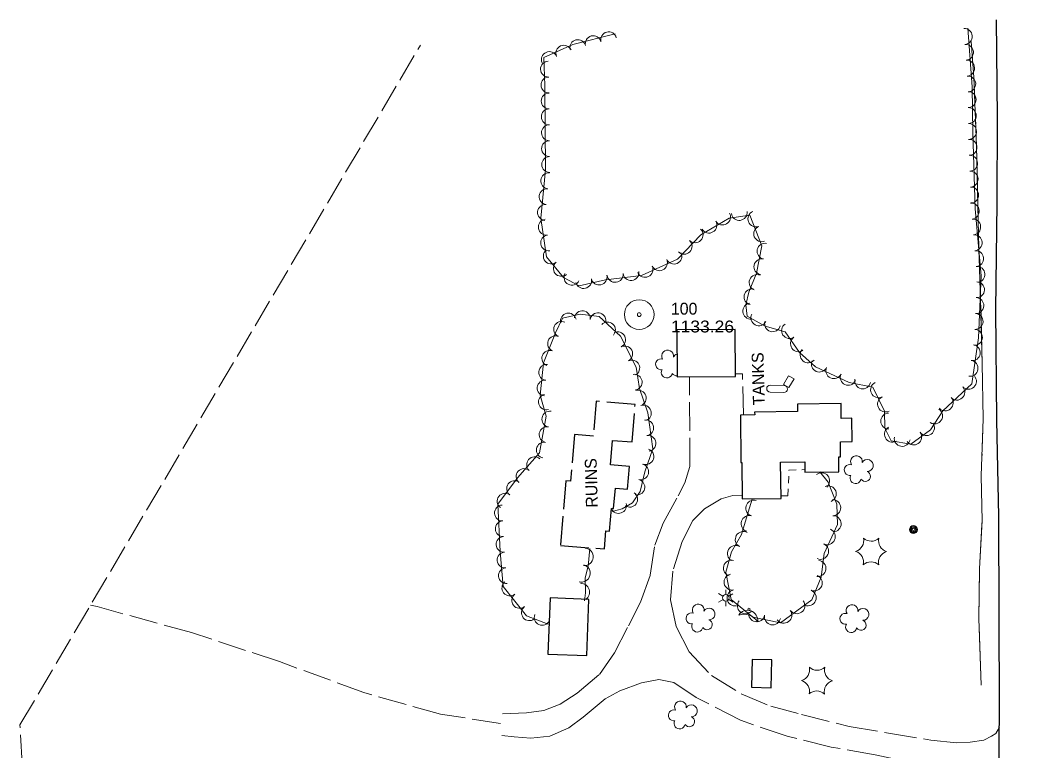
# Model space of a CAD drawing. Extents: x 296527 to 298902, y 45711 to 46924.
# Drawn here: x 297194 to 297699, y 46546 to 46914 of the extents above; entities that cross this region are included whole.
import ezdxf

# ---------------------------------------------------------------- set-up
doc = ezdxf.new("R2010")
doc.units = 0
doc.header["$LTSCALE"] = 2.4
doc.linetypes.add('LONG_DASHED', pattern=[7.5, 6, -1.5])
doc.linetypes.add('SHORT_DASHED', pattern=[2.7, 1.5, -1.2])
for name, color, linetype, lineweight in [('11', 7, 'Continuous', 25), ('12', 7, 'Continuous', 13), ('14', 7, 'Continuous', 13), ('17', 7, 'LONG_DASHED', 13), ('18', 7, 'Continuous', 13), ('19', 7, 'Continuous', 13), ('4', 7, 'Continuous', 13), ('6', 7, 'Continuous', 13)]:
    doc.layers.add(name, color=color, linetype=linetype, lineweight=lineweight)

msp = doc.modelspace()

# ---------------------------------------------------------------- linework, layer by layer
at = {"layer": '11'}
msp.add_lwpolyline([(297692.464, 45930.163), (297697.156, 45968.357), (297698.514, 45980.054), (297696.031, 46018.05), (297694.427, 46060.322), (297693.685, 46107.184), (297690.534, 46150.067), (297687.278, 46195.408), (297686.38, 46235.432), (297685.597, 46280.048), (297686.183, 46328.589), (297686.8, 46372.646), (297687.26, 46409.842), (297687.847, 46444.997), (297688.271, 46486.097), (297688.584, 46512.367), (297689.185, 46567.008), (297689.042, 46613.28), (297688.816, 46663.597), (297687.713, 46712.034), (297687.351, 46767.843), (297688.042, 46821.878), (297688.175, 46864.957), (297687.551, 46914.245)], dxfattribs=at)
at = {"layer": '12'}
for p, q in [((297573.172, 46726.37), (297580.192, 46726.161)), ((297580.272, 46729.661), (297573.178, 46729.867))]:
    msp.add_line(p, q, dxfattribs=at)
at = {"layer": '12', "lineweight": 25}
for points in [[(297526.256, 46734.025), (297555.648, 46734.199), (297555.507, 46757.95), (297526.115, 46757.776)], [(297590.797, 46685.955), (297607.985, 46686.138), (297607.905, 46693.67), (297608.8, 46693.679), (297608.719, 46701.263), (297614.672, 46701.326), (297614.547, 46713.1), (297609.168, 46713.043), (297609.088, 46720.521), (297587.031, 46720.286), (297587.072, 46716.494), (297565.396, 46716.264), (297565.411, 46714.818), (297558.239, 46714.742), (297558.493, 46690.847), (297558.925, 46690.852), (297559.121, 46672.451), (297578.735, 46672.66), (297578.54, 46690.974), (297590.742, 46691.104)], [(297480.573, 46593.27), (297481.666, 46621.61), (297462.012, 46622.368), (297460.919, 46594.028)], [(297573.798, 46577.052), (297574.068, 46591.098), (297564.095, 46591.29), (297563.825, 46577.244)]]:
    msp.add_lwpolyline(points, close=True, dxfattribs=at)
at = {"layer": '12'}
msp.add_lwpolyline([(297582.685, 46728.592), (297585.287, 46732.964), (297582.551, 46734.592), (297579.949, 46730.22)], close=True, dxfattribs=at)
at = {"layer": '12', "linetype": 'LONG_DASHED', "lineweight": 25}
msp.add_lwpolyline([(297489.514, 46647.097), (297490.265, 46656.206), (297492.09, 46656.056), (297493.039, 46667.569), (297494.139, 46667.479), (297494.996, 46677.871), (297501.135, 46677.364), (297502.081, 46688.832), (297492.575, 46689.615), (297493.593, 46701.964), (297503.416, 46701.154), (297504.975, 46720.057), (297485.32, 46721.678), (297483.875, 46704.149), (297474.273, 46704.941), (297472.328, 46681.348), (297469.939, 46681.545), (297467.25, 46648.933)], close=True, dxfattribs=at)
at = {"layer": '12'}
msp.add_circle((297562.51, 46616.687), 0.562, dxfattribs=at)
for centre, radius, start, end in [((297573.235, 46728.119), 1.75, 91.87738, 267.92471), ((297580.22, 46727.911), 1.75, 269.05923, 88.30992), ((297561.752, 46610.957), 5.217, 353.45511, 147.75346), ((297559.854, 46605.565), 8.553, 34.11068, 107.09479)]:
    msp.add_arc(centre, radius, start, end, dxfattribs=at)
at = {"layer": '14'}
for p, q in [((297550.824, 46624.034), (297550.828, 46626.555)), ((297549.398, 46623.261), (297547.133, 46624.568)), ((297549.432, 46621.56), (297547.162, 46620.304)), ((297550.817, 46620.758), (297550.811, 46618.155)), ((297552.288, 46621.553), (297554.512, 46620.246)), ((297552.291, 46623.19), (297554.436, 46624.488))]:
    msp.add_line(p, q, dxfattribs=at)
for centre, radius in [((297645.625, 46656.885), 2.018), ((297645.612, 46656.882), 1.518), ((297645.652, 46656.889), 1.008), ((297645.642, 46656.893), 0.502), ((297550.842, 46622.394), 1.641)]:
    msp.add_circle(centre, radius, dxfattribs=at)
at = {"layer": '17'}
for points in [[(297437.981, 46563.897), (297450.11, 46564.411), (297458.821, 46565.515), (297467.111, 46568.774), (297475.644, 46574.285), (297486.978, 46583.781), (297494.557, 46594.588), (297501.638, 46608.275), (297507.657, 46620.206), (297512.622, 46633.911), (297514.949, 46649.077), (297519.099, 46660.171), (297526.706, 46673.921), (297530.165, 46680.571), (297532.57, 46688.821), (297532.546, 46734.062)], [(297559.773, 46714.758), (297559.219, 46735.502), (297555.64, 46735.476)], [(297559.102, 46674.266), (297554.412, 46674.044), (297548.404, 46672.462), (297540.069, 46667.298), (297534.091, 46661.458), (297528.78, 46650.856), (297523.979, 46635.837), (297522.815, 46621.498), (297525.759, 46607.917), (297532.218, 46595.231), (297543.627, 46583.261), (297558.5, 46574), (297573.5, 46567.687), (297589.143, 46563.515), (297613.239, 46557.387), (297632.991, 46554.142), (297654.457, 46550.569), (297667.375, 46549.178), (297674.251, 46549.466), (297681.249, 46550.571), (297685.057, 46552.505), (297687.345, 46553.987), (297689.076, 46557.133)], [(297436.873, 46558.953), (297406.558, 46563.726), (297367.894, 46574.612), (297325.194, 46590.242), (297280.781, 46604.869), (297233.165, 46617.978), (297229.799, 46618.805)], [(297688.597, 46513.58), (297682.72, 46521.77), (297672.439, 46530.224), (297657.436, 46536.781), (297626.307, 46543.076), (297604.151, 46547.075), (297581.792, 46552.565), (297558.17, 46560.59), (297535.85, 46572.095), (297524.577, 46579.691), (297517.014, 46581.225), (297508.174, 46579.446), (297497.182, 46575.442), (297489.816, 46571.477), (297478.71, 46562.147), (297471.422, 46556.804), (297461.859, 46552.581), (297452.337, 46551.488), (297443.844, 46552.291), (297437.568, 46552.903)]]:
    msp.add_lwpolyline(points, dxfattribs=at)
at = {"layer": '17', "linetype": 'SHORT_DASHED'}
msp.add_lwpolyline([(297578.721, 46673.93), (297582.239, 46673.867), (297582.724, 46686.898), (297590.784, 46687.158)], dxfattribs=at)
at = {"layer": '18'}
for points in [[(297494.967, 46907.292), (297473.503, 46901.804), (297458.868, 46895.318), (297459.358, 46881.106), (297459.754, 46838.496), (297457.296, 46814.107), (297460.21, 46794.645), (297468.811, 46784.157), (297476.755, 46779.995), (297490.052, 46783.069), (297508.226, 46785.22), (297526.464, 46793.534), (297538.236, 46805.793), (297552.512, 46814.242), (297563.005, 46815.637), (297569.078, 46800.254), (297566.27, 46786.356), (297562.464, 46776.778), (297560.968, 46770.44), (297561.57, 46764.618), (297570.749, 46759.705), (297580.892, 46756.803), (297588.03, 46746.284), (297596.158, 46739.021), (297613.213, 46731.254), (297625.062, 46728.759), (297630.978, 46716.703), (297631.118, 46708.141), (297634.381, 46701.73), (297644.384, 46700.083), (297654.345, 46707.283), (297660.562, 46716.94), (297675.232, 46730.497), (297678.571, 46753.673), (297679.957, 46785.069), (297676.917, 46818.812), (297675.604, 46857.472), (297675.32, 46880.499), (297673.164, 46910.066)], [(297493.355, 46665.997), (297498.452, 46667.371), (297503.595, 46670.467), (297507.486, 46676.048), (297509.975, 46686.136), (297514.011, 46697.628), (297511.357, 46715.877), (297507.157, 46728.184), (297505.471, 46738.908), (297497.617, 46754.529), (297486.762, 46764.461), (297477.137, 46765.658), (297468.233, 46763.708), (297464.702, 46756.266), (297458.64, 46741.026), (297457.057, 46724.757), (297459.973, 46714.094), (297456.729, 46695.684), (297445.527, 46683.069), (297435.613, 46669.815), (297436.83, 46645.828), (297438.327, 46628.222), (297450.066, 46613.383), (297460.974, 46609.216)], [(297564.079, 46672.212), (297562.16, 46665.727), (297558.702, 46654.458), (297553.771, 46645.695), (297550.914, 46635.435), (297553.495, 46621.53), (297564.466, 46612.615), (297578.528, 46609.871), (297594.292, 46621.406), (297598.955, 46632.784), (297600.493, 46644.782), (297607.192, 46659.432), (297606.9, 46669.724), (297602.575, 46680.808), (297598.298, 46686)], [(297479.429, 46620.948), (297479.851, 46624.939), (297479.669, 46632.587), (297481.273, 46638.504), (297482.074, 46647.367)]]:
    msp.add_lwpolyline(points, dxfattribs=at)
for centre, radius, start, end in [((297491.6, 46904.264), 4.012, 14.35, 194.33468), ((297671.361, 46905.913), 4.012, 274.17824, 94.16292), ((297476.055, 46900.289), 4.012, 14.35, 194.33468), ((297483.828, 46902.277), 4.012, 14.35, 194.33468), ((297461.602, 46894.233), 4.012, 23.90983, 203.8945), ((297468.936, 46897.483), 4.012, 23.90983, 203.8945), ((297671.945, 46897.911), 4.012, 274.17824, 94.16292), ((297461.172, 46889.43), 4.012, 91.98232, 271.96699), ((297672.528, 46889.91), 4.012, 274.17824, 94.16292), ((297461.448, 46881.412), 4.012, 91.98232, 271.96699), ((297673.112, 46881.908), 4.012, 274.17824, 94.16292), ((297461.53, 46873.337), 4.012, 90.54013, 270.52481), ((297673.3, 46874.017), 4.012, 270.71427, 90.69895), ((297461.605, 46865.315), 4.012, 90.54013, 270.52481), ((297673.399, 46865.995), 4.012, 270.71427, 90.69895), ((297673.498, 46857.973), 4.012, 270.71427, 90.69895), ((297461.679, 46857.292), 4.012, 90.54013, 270.52481), ((297461.754, 46849.27), 4.012, 90.54013, 270.52481), ((297673.76, 46849.909), 4.012, 271.95284, 91.93751), ((297461.828, 46841.248), 4.012, 90.54013, 270.52481), ((297674.032, 46841.891), 4.012, 271.95284, 91.93751), ((297461.313, 46833.022), 4.012, 84.25264, 264.23732), ((297674.305, 46833.873), 4.012, 271.95284, 91.93751), ((297460.508, 46825.039), 4.012, 84.25264, 264.23732), ((297674.577, 46825.855), 4.012, 271.95284, 91.93751), ((297674.907, 46817.722), 4.012, 275.1557, 95.14038), ((297459.704, 46817.057), 4.012, 84.25264, 264.23732), ((297549.205, 46814.725), 4.012, 210.62609, 30.61076), ((297557.611, 46817.038), 4.012, 187.58049, 7.56516), ((297566.008, 46813.748), 4.012, 111.5511, 291.53578), ((297460.09, 46809.625), 4.012, 98.52317, 278.50784), ((297542.301, 46810.639), 4.012, 210.62609, 30.61076), ((297675.627, 46809.732), 4.012, 275.1557, 95.14038), ((297535.297, 46805.764), 4.012, 226.16863, 46.15331), ((297568.954, 46806.285), 4.012, 111.5511, 291.53578), ((297461.278, 46801.691), 4.012, 98.52317, 278.50784), ((297529.74, 46799.977), 4.012, 226.16863, 46.15331), ((297570.667, 46797.518), 4.012, 78.58519, 258.56987), ((297676.347, 46801.742), 4.012, 275.1557, 95.14038), ((297462.603, 46795.039), 4.012, 129.36216, 309.34684), ((297524.586, 46794.986), 4.012, 204.51407, 24.49875), ((297677.067, 46793.751), 4.012, 275.1557, 95.14038), ((297467.69, 46788.835), 4.012, 129.36216, 309.34684), ((297517.286, 46791.658), 4.012, 204.51407, 24.49875), ((297569.078, 46789.654), 4.012, 78.58519, 258.56987), ((297473.058, 46784.302), 4.012, 152.35684, 332.34151), ((297494.917, 46785.759), 4.012, 186.75755, 6.74223), ((297502.884, 46786.702), 4.012, 186.75755, 6.74223), ((297509.986, 46788.33), 4.012, 204.51407, 24.49875), ((297677.786, 46785.761), 4.012, 275.1557, 95.14038), ((297478.961, 46782.66), 4.012, 193.02462, 13.0093), ((297486.777, 46784.467), 4.012, 193.02462, 13.0093), ((297566.658, 46781.646), 4.012, 68.33633, 248.321), ((297677.544, 46778.029), 4.012, 267.47994, 87.46462), ((297564.06, 46774.397), 4.012, 76.72684, 256.71152), ((297563.413, 46767.213), 4.012, 95.91112, 275.89579), ((297677.191, 46770.015), 4.012, 267.47994, 87.46462), ((297471.259, 46762.238), 3.98, 12.36057, 192.34524), ((297478.354, 46763.407), 3.98, 352.91855, 172.90323), ((297486.252, 46762.425), 3.98, 352.91855, 172.90323), ((297676.837, 46762), 4.012, 267.47994, 87.46462), ((297467.835, 46758.01), 3.98, 64.62476, 244.60944), ((297491.04, 46757.723), 3.98, 317.55008, 137.53476), ((297567.525, 46763.812), 4.012, 151.85004, 331.83471), ((297574.444, 46760.832), 4.012, 164.04138, 344.02606), ((297496.183, 46752.744), 3.98, 296.70021, 116.68489), ((297583.031, 46757.39), 4.012, 124.16776, 304.15243), ((297676.483, 46753.985), 4.012, 267.47994, 87.46462), ((297464.775, 46750.813), 3.98, 68.31653, 248.30121), ((297587.536, 46750.752), 4.012, 124.16776, 304.15243), ((297461.833, 46743.417), 3.98, 68.31653, 248.30121), ((297499.758, 46745.633), 3.98, 296.70021, 116.68489), ((297521.448, 46744.57), 2.974, 349.94487, 211.17875), ((297592.448, 46745.152), 4.012, 138.2244, 318.20907), ((297675.38, 46746.249), 4.012, 261.80939, 81.79407), ((297503.333, 46738.522), 3.98, 296.70021, 116.68489), ((297518.088, 46740.376), 2.777, 72.91576, 280.68875), ((297526.964, 46742.61), 2.975, 105.1299, 150.56896), ((297598.094, 46740.447), 4.012, 155.52272, 335.50739), ((297674.236, 46738.308), 4.012, 261.80939, 81.79407), ((297460.272, 46736.289), 3.98, 84.45018, 264.43486), ((297521.004, 46736.239), 2.783, 149.59278, 350.60382), ((297525.957, 46737.18), 2.611, 212.30092, 276.51184), ((297605.395, 46737.122), 4.012, 155.52272, 335.50739), ((297459.501, 46728.367), 3.98, 84.45018, 264.43486), ((297504.554, 46731.33), 3.98, 278.94242, 98.9271), ((297612.697, 46733.796), 4.012, 155.52272, 335.50739), ((297620.005, 46731.97), 4.012, 168.11681, 348.10149), ((297628.01, 46727.518), 4.012, 116.14531, 296.12999), ((297673.488, 46731.745), 4.012, 222.74964, 42.73432), ((297506.622, 46723.302), 3.98, 288.85085, 108.83553), ((297667.596, 46726.3), 4.012, 222.74964, 42.73432), ((297460.156, 46721.323), 3.98, 105.30233, 285.28701), ((297631.544, 46720.315), 4.012, 116.14531, 296.12999), ((297661.704, 46720.855), 4.012, 222.74964, 42.73432), ((297461.845, 46712.714), 3.98, 80.01424, 259.99892), ((297509.193, 46715.77), 3.98, 288.85085, 108.83553), ((297633.16, 46711.709), 4.012, 90.94444, 270.92912), ((297656.346, 46714.27), 4.012, 237.23497, 57.21964), ((297510.355, 46708.292), 3.98, 278.28233, 98.267), ((297652.252, 46708.361), 4.012, 215.86778, 35.85246), ((297460.464, 46704.876), 3.98, 80.01424, 259.99892), ((297635.025, 46705.093), 4.012, 116.98234, 296.96702), ((297645.75, 46703.661), 4.012, 215.86778, 35.85246), ((297459.083, 46697.037), 3.98, 80.01424, 259.99892), ((297511.501, 46700.416), 3.98, 278.28233, 98.267), ((297639.97, 46702.938), 4.012, 170.65777, 350.64244), ((297510.442, 46693.752), 3.98, 250.65634, 70.64102), ((297454.158, 46689.651), 3.98, 48.40289, 228.38757), ((297616.841, 46691.214), 2.974, 349.94487, 211.17875), ((297622.357, 46689.254), 2.975, 267.59569, 150.56896), ((297448.873, 46683.7), 3.98, 48.40289, 228.38757), ((297507.804, 46686.035), 3.98, 256.14796, 76.13263), ((297599.24, 46681.508), 4.068, 309.48824, 129.47292), ((297613.481, 46687.02), 2.777, 72.91576, 280.68875), ((297621.35, 46683.824), 2.611, 212.30092, 70.23353), ((297444.041, 46677.605), 3.98, 53.21115, 233.19583), ((297505.898, 46678.307), 3.98, 256.14796, 76.13263), ((297616.397, 46682.883), 2.783, 149.59278, 350.60382), ((297439.274, 46671.231), 3.98, 53.21115, 233.19583), ((297502.262, 46672.198), 3.98, 235.12396, 55.10864), ((297602.582, 46674.935), 4.068, 291.32349, 111.30817), ((297564.966, 46667.707), 4.068, 73.52346, 253.50814), ((297604.82, 46667.954), 4.068, 271.63279, 91.61747), ((297437.928, 46665.294), 3.98, 92.91212, 272.8968), ((297496.656, 46669.044), 3.98, 204.22138, 15.07897), ((297438.331, 46657.345), 3.98, 92.91212, 272.8968), ((297562.6, 46659.903), 4.068, 72.94853, 252.93321), ((297605.051, 46659.823), 4.068, 271.63279, 91.61747), ((297559.682, 46651.858), 4.068, 60.64091, 240.62558), ((297602.061, 46653.331), 4.068, 245.43448, 65.41916), ((297438.735, 46649.396), 3.98, 92.91212, 272.8968), ((297614.801, 46651.356), 5.725, 286.73253, 12.49744), ((297624.314, 46656.763), 5.725, 226.73254, 312.49745), ((297633.752, 46651.231), 5.725, 166.73254, 252.49746), ((297439.286, 46641.528), 3.98, 94.86771, 274.85239), ((297479.354, 46643.146), 4.449, 264.84354, 84.82822), ((297555.693, 46644.769), 4.068, 60.64091, 240.62558), ((297598.678, 46645.933), 4.068, 245.43448, 65.41916), ((297614.728, 46640.415), 5.725, 346.73253, 72.49744), ((297633.679, 46640.288), 5.725, 106.73254, 192.49745), ((297553.676, 46637.418), 4.068, 74.44727, 254.43194), ((297597.384, 46637.274), 4.068, 262.70287, 82.68754), ((297624.166, 46634.881), 5.725, 46.73253, 132.49744), ((297439.961, 46633.598), 3.98, 94.86771, 274.85239), ((297477.862, 46634.821), 4.449, 254.84025, 74.82493), ((297441.661, 46627.365), 3.98, 128.35487, 308.33954), ((297554.008, 46630.433), 4.068, 100.52304, 280.50772), ((297595.514, 46630.001), 4.068, 247.72257, 67.70725), ((297477.513, 46625.32), 4.449, 304.93335, 91.35555), ((297555.492, 46622.435), 4.068, 100.52304, 280.50772), ((297592.429, 46622.474), 4.068, 247.72257, 67.70725), ((297446.599, 46621.123), 3.98, 128.35487, 308.33954), ((297560.742, 46618.384), 4.068, 140.91046, 320.89514), ((297586.698, 46618.487), 4.068, 216.20174, 36.18641), ((297451.538, 46614.88), 3.98, 128.35487, 308.33954), ((297533.506, 46612.082), 2.777, 72.91576, 280.68875), ((297536.866, 46616.276), 2.974, 349.94487, 211.17875), ((297542.382, 46614.316), 2.975, 267.59569, 150.56896), ((297566.45, 46614.397), 4.068, 168.96596, 348.95063), ((297580.134, 46613.684), 4.068, 216.20174, 36.18641), ((297614.615, 46616.018), 2.974, 349.94487, 211.17875), ((297620.131, 46614.058), 2.975, 267.59569, 150.56896), ((297458, 46612.582), 3.98, 159.10014, 333.63628), ((297541.375, 46608.886), 2.611, 212.30092, 70.23353), ((297574.434, 46612.839), 4.068, 168.96596, 348.95063), ((297611.255, 46611.824), 2.777, 72.91576, 280.68875), ((297619.124, 46608.628), 2.611, 212.30092, 70.23353), ((297536.422, 46607.945), 2.783, 149.59278, 350.60382), ((297614.171, 46607.687), 2.783, 149.59278, 350.60382), ((297587.456, 46586.164), 5.725, 286.73253, 12.49744), ((297596.969, 46591.571), 5.725, 226.73254, 312.49745), ((297606.407, 46586.039), 5.725, 166.73254, 252.49746), ((297587.383, 46575.223), 5.725, 346.73253, 72.49744), ((297606.334, 46575.096), 5.725, 106.73254, 192.49745), ((297596.821, 46569.689), 5.725, 46.73253, 132.49744), ((297527.905, 46567.322), 2.974, 349.94487, 211.17875), ((297524.545, 46563.128), 2.777, 72.91576, 280.68875), ((297533.421, 46565.362), 2.975, 267.59569, 150.56896), ((297527.461, 46558.991), 2.783, 149.59278, 350.60382), ((297532.414, 46559.932), 2.611, 212.30092, 70.23353)]:
    msp.add_arc(centre, radius, start, end, dxfattribs=at)
at = {"layer": '19'}
for p, q in [((297676.883, 46867.826), (297676.804, 46869.858)), ((297677.121, 46861.732), (297677.042, 46863.763)), ((297677.358, 46855.637), (297677.279, 46857.669)), ((297679.109, 46786.538), (297679.042, 46788.57)), ((297679.31, 46780.442), (297679.243, 46782.474)), ((297679.511, 46774.347), (297679.444, 46776.378)), ((297680.393, 46740.82), (297679.634, 46770.283)), ((297680.641, 46705.261), (297680.708, 46707.293)), ((297680.438, 46699.166), (297680.506, 46701.197)), ((297680.236, 46693.07), (297680.303, 46695.102)), ((297678.895, 46624.014), (297678.93, 46626.046)), ((297678.792, 46617.919), (297678.826, 46619.95)), ((297679.891, 46578.316), (297678.839, 46607.762))]:
    msp.add_line(p, q, dxfattribs=at)
for points in [[(297679.891, 46578.316), (297678.69, 46611.947), (297679.119, 46637.149), (297680.376, 46661.267), (297679.933, 46683.966), (297680.891, 46712.795), (297680.393, 46740.808), (297679.596, 46771.773), (297678.49, 46805.331), (297677.551, 46850.682), (297676.2, 46885.371), (297674.874, 46903.342)], [(297676.646, 46873.921), (297676.2, 46885.371), (297674.874, 46903.342)], [(297678.143, 46822.102), (297677.551, 46850.682), (297677.516, 46851.574)], [(297678.908, 46792.634), (297678.49, 46805.331), (297678.143, 46822.102)], [(297680.843, 46711.357), (297680.891, 46712.795), (297680.393, 46740.808), (297680.393, 46740.82)], [(297680.286, 46659.544), (297680.376, 46661.267), (297679.933, 46683.966), (297680.1, 46689.006)], [(297678.999, 46630.109), (297679.119, 46637.149), (297680.286, 46659.544)], [(297678.694, 46611.823), (297678.69, 46611.947), (297678.722, 46613.855)]]:
    msp.add_lwpolyline(points, dxfattribs=at)
at = {"layer": '4', "linetype": 'LONG_DASHED'}
msp.add_lwpolyline([(297236.947, 45856.087), (297194.081, 46558.227), (297396.47, 46901.483)], dxfattribs=at)
at = {"layer": '6'}
for radius in [7.5, 0.96]:
    msp.add_circle((297507.068, 46765.452), radius, dxfattribs=at)

# ---------------------------------------------------------------- texts
at = {"layer": '12'}
for s, rotation, p in [('TANKS', 91.521, (297570.558, 46719.713)), ('RUINS', 91.455, (297486.136, 46668.05))]:
    msp.add_text(s, height=6, rotation=rotation, dxfattribs=at).set_placement(p)
at = {"layer": '6'}
msp.add_text('100', height=6, dxfattribs=at).set_placement((297523.068, 46765.452))
at = {"layer": '6', "width": 1.1}
msp.add_text('1133.26', height=6, dxfattribs=at).set_placement((297523.068, 46756.452))

doc.saveas('drawing.dxf')
